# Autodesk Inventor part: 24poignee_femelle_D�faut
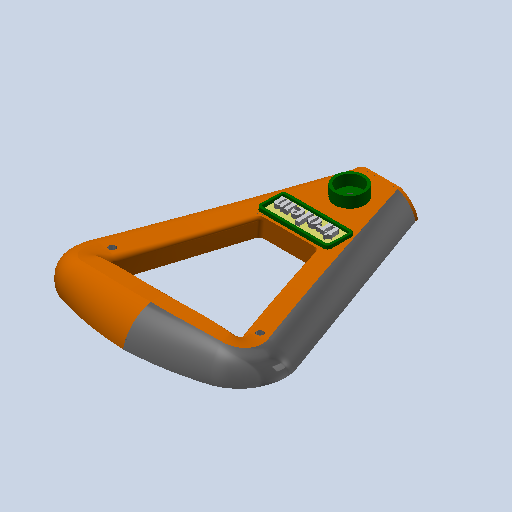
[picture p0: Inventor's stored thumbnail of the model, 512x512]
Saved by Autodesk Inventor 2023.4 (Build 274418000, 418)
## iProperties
Created: 2011-01
Part Number: 24poignee_femelle_D�faut
Document SubType Name: Modeling
Designer: eric
Density: 1 g/cm^3
Mass: 71.4336 g
Surface Area: 665.835 cm^2
Volume: 71.4336 cm^3
Material: Générique
Appearance: Caoutchouc - Noir - Version 1.1
Author: eric
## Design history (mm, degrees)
feature "Base1"
node "Corps solides"
node "Corps surfaciques"
node "Solide1"
